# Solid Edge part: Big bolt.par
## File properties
Author: m_hel
Template: iso metric part.par
Last saved by: m_hel
Revision: 2
Application: Solid Edge
Accuracy: 0,990
Username: m_hel
Material: Rubber
Face Style: Black (dull)
Fill Style: Normal
Virtual Style: Normal
Grouping: Uncategorized
LibraryName: Custom Materials
Coef. of Thermal Exp: 0.0
Thermal Conductivity: 0.0
Specific Heat: 0.0
Modulus of Elasticity: 0.0
Poisson's Ratio: 0.0
Yield Stress: 0.0
Ultimate Stress: 0.0
Elongation: 0.0
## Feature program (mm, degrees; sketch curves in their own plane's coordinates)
sketch for "unnamed Protrusion 1" plane through (0, 0, 0) normal (1, 0, 0) x-axis (0, 1, 0)
  circle centre (0, 0) radius 15
extrude "unnamed Protrusion 1" add finite 125 along +normal
sketch for "ExtrudedProtrusion_2" plane through (125, 0, 0) normal (1, 0, 0) x-axis (0, 1, 0)
  circle centre (0, 0) radius 25
extrude "ExtrudedProtrusion_2" add finite 5 along +normal
sketch for "ExtrudedProtrusion_3" plane through (130, 0, 0) normal (1, 0, 0) x-axis (0, 1, 0)
  line (18, 10.3923) -> (0, 20.7846)
  line (0, 20.7846) -> (-18, 10.3923)
  line (-18, 10.3923) -> (-18, -10.3923)
  line (-18, -10.3923) -> (0, -20.7846)
  line (0, -20.7846) -> (18, -10.3923)
  line (18, -10.3923) -> (18, 10.3923)
extrude "ExtrudedProtrusion_3" add finite 20 along +normal
body pattern "unnamed BodyPattern 1"
pattern "unnamed Pattern 1"
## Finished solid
Body 1: solid body, 21 faces, 42 edges, 24 vertices.
  Faces by surface: plane 18, cylinder 3
  Edges by curve: line 36, circle 6
Bounding box of the edges (mm): 300.000 x 50.000 x 50.000, from (-150, -25, -25) to (150, 25, 25).
Cylindrical faces by radius (mm): R15 x1, R25 x2
Planar faces by outward normal: +x 3, +y 2, -x 3, -y 2, oblique 8
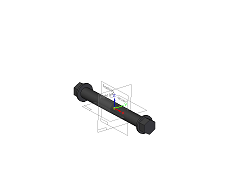
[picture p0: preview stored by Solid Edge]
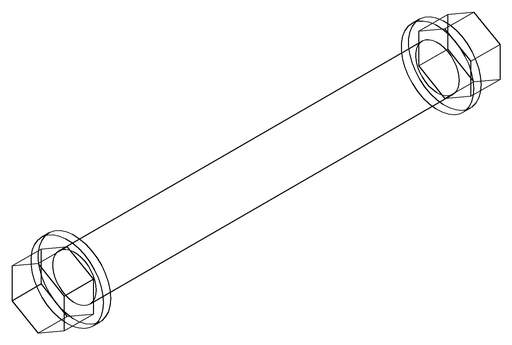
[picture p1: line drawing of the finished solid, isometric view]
